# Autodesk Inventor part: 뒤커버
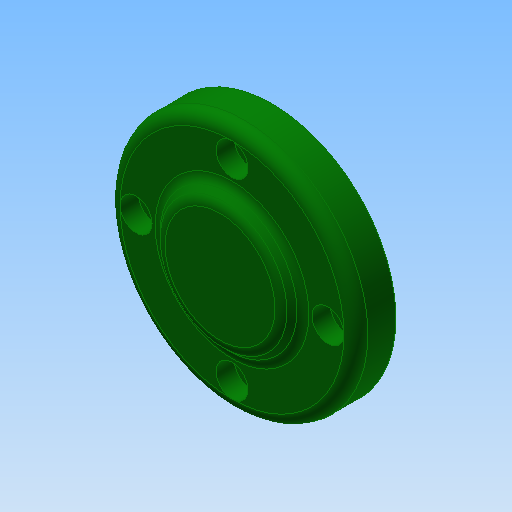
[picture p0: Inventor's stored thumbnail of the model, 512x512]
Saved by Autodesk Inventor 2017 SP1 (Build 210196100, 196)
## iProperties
Created: 2015-09
Part Number: 뒤커버
Material: 알루미늄 6061
Document SubType Name: Modeling
Designer: mduedu
Density: 1 g/cm^3
Appearance: 진녹색
Author: mduedu
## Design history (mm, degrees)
sketch "스케치1"
  geometry: L1 (0, 9)-(0, -9); L2 (0, 9)-(15, 9); L3 (15, 9)-(18, 6); L4 (18, 6)-(31, 6); L5 (31, 6)-(31, -4); L6 (31, -4)-(17.5, -4); L7 (17.5, -4)-(17.5, -9); L8 (17.5, -9)-(0, -9); 2 further points
  constraints: 16 end point, 3 parallel, 2 perpendicular, 1 coincident, 1 horizontal, 1 midpoint, 1 vertical
  dimensions: "d1" = 3 distance between parallel lines of L4 L2; "d2" = 10 distance of L4.end L5.end; "d3" = 36 diameter of L3.end L1; "d4" = 35 diameter of L7 L1; "d5" = 62 diameter of L5 L1; "d7" = 45 deg angle of L3 L5; "d48" = 5 distance between parallel lines of L6 L8
revolve "회전1" sketch "스케치1" stored, may be unused: angle "d8" = 90 deg
hole "구멍1" diameter "d11" = 30; stored, may be unused: countersink angle "d15" = 90 deg, drill point angle "d17" = 0 deg; dims "d12" = 6, "d13" = 4, "d14" = 2, "d16" = 10, "d49" = 10, "d50" = 10
fillet "모깎기1" dims "d18" = 3
fillet "모깎기2" dims "d25" = 3
fillet "모깎기3" dims "d26" = 3
sketch "스케치3"
  geometry: 4 further points
hole "구멍2" sketch "스케치3" at (-24, 0), (0, -24), (24, 0), (0, 24) diameter "d35" = 4.5; stored, may be unused: countersink angle "d39" = 90 deg, drill point angle "d41" = 0 deg; dims "d36" = 6, "d37" = 8, "d38" = 4.6, "d40" = 8
chamfer "모따기3" distance "d42" = 1; stored, may be unused: second distance "d43" = 2, angle "d44" = 45 deg
fillet "모깎기4" dims "d45" = 3
node "솔리드1"
sketch "스케치2" dims "d27" = 48
  geometry: 6 further points
  constraints: 2 vertical alignment, 1 coincident, 7 other
  dimensions: "d33" = 360 deg dimension on point (0, 0) point (0, 24) (derived)
